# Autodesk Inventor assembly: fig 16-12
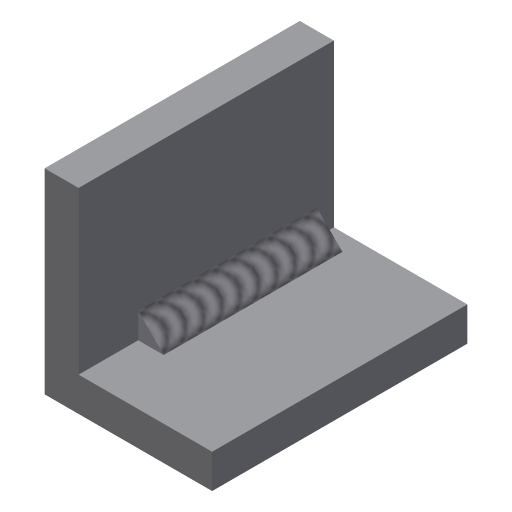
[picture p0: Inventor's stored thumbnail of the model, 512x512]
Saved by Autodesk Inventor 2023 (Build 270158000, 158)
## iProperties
Created: 2009-05
Part Number: fig 16-12
Document SubType Name: Weldment
Designer: Sham
Weld Material: Welded Aluminum-6061
Author: Sham
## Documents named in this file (2)
- D:\PROJECTS\Project 2022\Autodesk Inventor For Professional 2023\RESOURCES INVENTOR 2023\RESOURCES INVENTOR 2023\Inventor_2023_Part\Inventor_2023_Part\c16_Inv_2023_prt\fig 16-12.iam
- D:\PROJECTS\Project 2022\Autodesk Inventor For Professional 2023\RESOURCES INVENTOR 2023\RESOURCES INVENTOR 2023\Inventor_2023_Part\Inventor_2023_Part\c16_Inv_2023_prt\Part3.ipt
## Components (1 placed, 1 different names)
1. Part3:1
